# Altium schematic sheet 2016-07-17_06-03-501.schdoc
size 231 x 111 mm; SheetNumber: 1; SheetTotal: 1
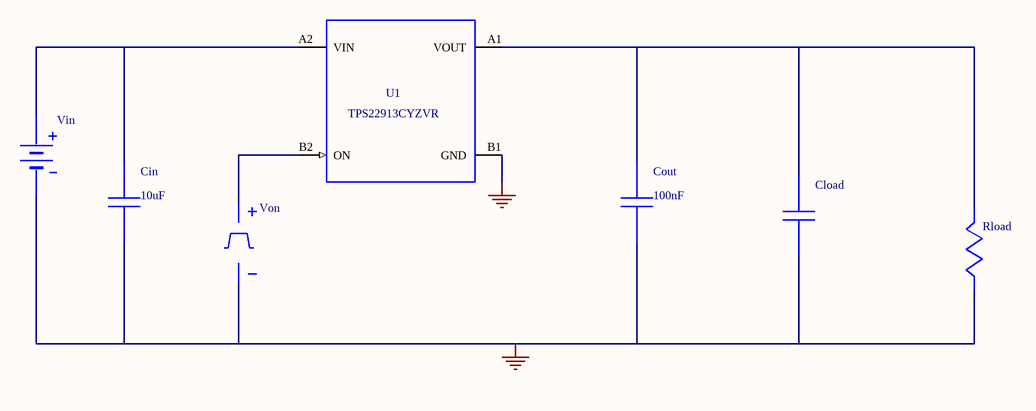
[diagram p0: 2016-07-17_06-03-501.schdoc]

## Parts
Cin  value 10uF  (hidden comment: GRM219R60J106KE19D)
Cload  GRM21BR71E104KA01L  (value not drawn)
Cout  value 100nF  (hidden comment: GRM155R60J104KA01D)
Rload  WB_LOAD_RESISTOR  (value not drawn)
U1  TPS22913CYZVR
Vin  WB_BATTERY  (value not drawn)
Von  WB_PRIM_PWL_VOLTAGE_SOURCE  (value not drawn)

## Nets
0: Cin.2 Cload.2 Cout.2 Rload.2 U1.B1(GND) Vin.2(-) Von.2(-)
NetCin_1: Cin.1 U1.A2(VIN) Vin.1(+)
NetCload_1: Cload.1 Cout.1 Rload.1 U1.A1(VOUT)
NetU1_B2: U1.B2(ON) Von.1(+)

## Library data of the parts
Cin = GRM219R60J106KE19D: GRM219R60J106KE1; Manufacturer Name: MuRata
Cload = GRM21BR71E104KA01L: WB_PRIMITIVE_CAP; Manufacturer Name: WB_PRIMITIVE_CAPACITOR
Cout = GRM155R60J104KA01D: GRM155R60J104KA0; Manufacturer Name: MuRata
U1 = TPS22913CYZVR: Manufacturer Name: Texas Instruments
Von = WB_PRIM_PWL_VOLTAGE_SOURCE: WB_PRIM_PWL_VOLT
